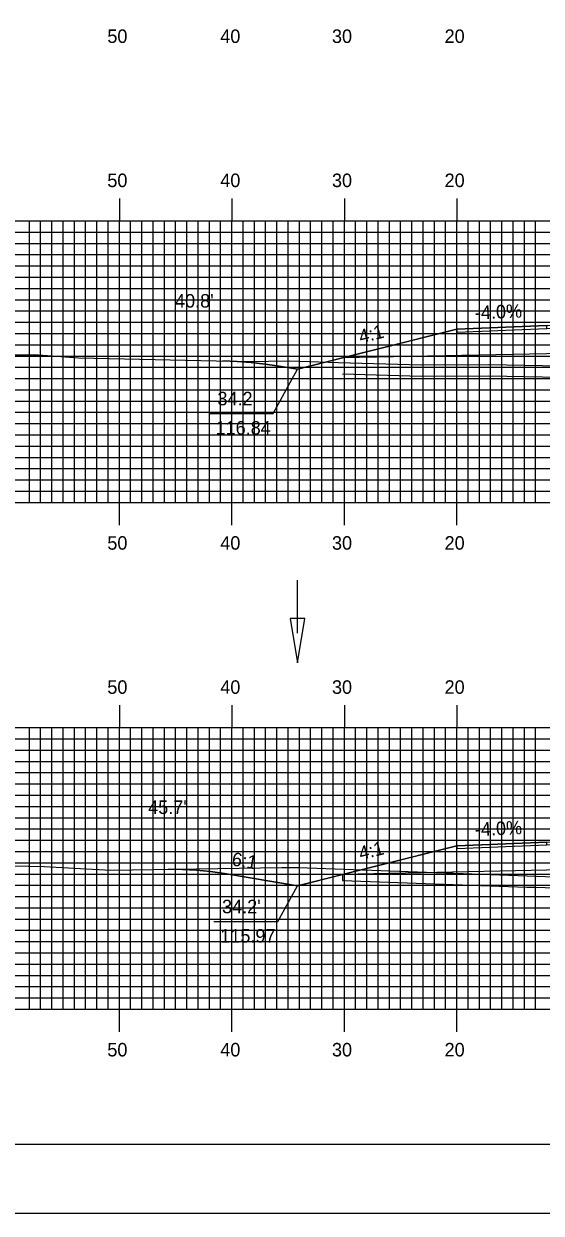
# Model space of a CAD drawing. Extents: x 1780680 to 1781023, y 442591 to 442811.
# Drawn here: x 1780786.9 to 1780832.9, y 442590.5 to 442696.2 of the extents above; entities that cross this region are included whole.
import ezdxf

# ---------------------------------------------------------------- set-up
doc = ezdxf.new("R2010")
doc.units = 0
for name, color, linetype in [('ANNOTATION', 7, 'Continuous'), ('BORDER', 7, 'Continuous'), ('D_Drainage_Ditch_Line', 7, 'Continuous'), ('D_Roadway_Centerline', 7, 'Continuous'), ('D_Roadway_Edge_Shoulder', 7, 'Continuous'), ('D_Roadway_SlopeLines', 7, 'Continuous'), ('D_Roadway_SubGrade', 7, 'Continuous'), ('D_Text_Standard', 7, 'Continuous'), ('GRUBBING IN FILL', 7, 'Continuous'), ('H_V ANNOTATION', 7, 'Continuous'), ('MAJOR', 7, 'Continuous'), ('MINOR', 7, 'Continuous'), ('PLOT BOUNDARY', 7, 'Continuous'), ('S_Roadway_Centerline', 7, 'Continuous')]:
    doc.layers.add(name, color=color, linetype=linetype)

msp = doc.modelspace()

# ---------------------------------------------------------------- linework, layer by layer
at = {"layer": 'ANNOTATION'}
for points in [[(1780803.36, 442661.56), (1780809.05, 442661.56), (1780811.21, 442665.51)], [(1780803.77, 442616.46), (1780809.46, 442616.46), (1780811.21, 442619.63)]]:
    msp.add_lwpolyline(points, dxfattribs=at)
at = {"layer": 'BORDER'}
msp.add_lwpolyline([(1780695.78, 442596.67), (1781015.78, 442596.67), (1781015.78, 442806.67), (1780695.78, 442806.67)], close=True, dxfattribs=at)
at = {"layer": 'D_Drainage_Ditch_Line'}
msp.add_line((1780811.21, 442642.05), (1780811.21, 442646.75), dxfattribs=at)
msp.add_lwpolyline([(1780811.86, 442643.36), (1780810.55, 442643.36), (1780811.21, 442639.42)], close=True, dxfattribs=at)
at = {"layer": 'D_Roadway_Centerline'}
for points in [[(1780804.59, 442666.23), (1780805.84, 442666.19), (1780807.09, 442666.1), (1780808.34, 442665.96), (1780809.59, 442665.78), (1780811.21, 442665.51), (1780815.21, 442666.51), (1780825.38, 442669.05), (1780833.38, 442669.37), (1780845.38, 442669.61), (1780857.38, 442669.37), (1780865.38, 442669.05), (1780875.56, 442666.51), (1780884.22, 442664.34)], [(1780799.73, 442621.09), (1780800.98, 442621.08), (1780802.23, 442621.02), (1780803.48, 442620.89), (1780804.73, 442620.71), (1780811.21, 442619.63), (1780815.21, 442620.63), (1780825.38, 442623.18), (1780833.38, 442623.5), (1780845.38, 442623.74), (1780857.38, 442623.5), (1780865.38, 442623.18), (1780875.56, 442620.63), (1780880.08, 442619.5)]]:
    msp.add_lwpolyline(points, dxfattribs=at)
at = {"layer": 'D_Roadway_Edge_Shoulder'}
for points in [[(1780833.38, 442669.37), (1780825.38, 442669.05), (1780825.38, 442668.8), (1780833.38, 442669.12)], [(1780833.38, 442623.5), (1780825.38, 442623.18), (1780825.38, 442622.93), (1780833.38, 442623.25)]]:
    msp.add_lwpolyline(points, close=True, dxfattribs=at)
at = {"layer": 'D_Roadway_SlopeLines'}
for points in [[(1780825.38, 442669.05), (1780811.21, 442665.51)], [(1780811.21, 442665.51), (1780809.59, 442665.78), (1780808.34, 442665.96), (1780807.09, 442666.1), (1780805.84, 442666.19), (1780804.59, 442666.23)], [(1780825.38, 442623.18), (1780811.21, 442619.63)], [(1780811.21, 442619.63), (1780804.73, 442620.71), (1780803.48, 442620.89), (1780802.23, 442621.02), (1780800.98, 442621.08), (1780799.73, 442621.09)]]:
    msp.add_lwpolyline(points, dxfattribs=at)
at = {"layer": 'D_Roadway_SubGrade'}
for points in [[(1780833.38, 442666.87), (1780815.21, 442666.51), (1780825.38, 442669.05), (1780825.38, 442668.8), (1780833.38, 442669.12), (1780845.38, 442669.36), (1780857.38, 442669.12), (1780865.38, 442668.8), (1780865.38, 442669.05), (1780875.56, 442666.51), (1780857.38, 442666.87), (1780845.38, 442667.11)], [(1780833.38, 442621), (1780815.21, 442620.63), (1780825.38, 442623.18), (1780825.38, 442622.93), (1780833.38, 442623.25), (1780845.38, 442623.49), (1780857.38, 442623.25), (1780865.38, 442622.93), (1780865.38, 442623.18), (1780875.56, 442620.63), (1780857.38, 442621), (1780845.38, 442621.24)]]:
    msp.add_lwpolyline(points, close=True, dxfattribs=at)
at = {"layer": 'GRUBBING IN FILL'}
msp.add_line((1780815.21, 442620.63), (1780815.21, 442620.09), dxfattribs=at)
msp.add_line((1780815.21, 442620.63), (1780815.21, 442620.09), dxfattribs=at)
for points in [[(1780815.21, 442665.08), (1780822.22, 442664.88), (1780828.21, 442664.92), (1780839.34, 442664.7), (1780845, 442664.49), (1780851.08, 442664.3), (1780863.46, 442663.89), (1780873.65, 442663.6), (1780875.56, 442663.55)], [(1780815.21, 442665.08), (1780822.22, 442664.88), (1780828.21, 442664.92), (1780839.34, 442664.7), (1780845, 442664.49), (1780851.08, 442664.3), (1780863.46, 442663.89), (1780873.65, 442663.6), (1780875.56, 442663.55)], [(1780815.21, 442620.09), (1780831.61, 442619.51), (1780832.44, 442619.49), (1780833.22, 442619.46), (1780853.78, 442619.04), (1780855.73, 442619.03), (1780857.73, 442618.96), (1780875.56, 442618.58)], [(1780815.21, 442620.09), (1780831.61, 442619.51), (1780832.44, 442619.49), (1780833.22, 442619.46), (1780853.78, 442619.04), (1780855.73, 442619.03), (1780857.73, 442618.96), (1780875.56, 442618.58)]]:
    msp.add_lwpolyline(points, dxfattribs=at)
at = {"layer": 'MAJOR'}
for p, q in [((1780795.38, 442680.67), (1780795.38, 442678.67)), ((1780805.38, 442680.67), (1780805.38, 442678.67)), ((1780815.38, 442680.67), (1780815.38, 442678.67)), ((1780825.38, 442680.67), (1780825.38, 442678.67)), ((1780705.38, 442678.67), (1780985.38, 442678.67)), ((1780705.38, 442678.67), (1780985.38, 442678.67)), ((1780795.38, 442653.67), (1780795.38, 442678.67)), ((1780805.38, 442653.67), (1780805.38, 442678.67)), ((1780815.38, 442653.67), (1780815.38, 442678.67)), ((1780825.38, 442653.67), (1780825.38, 442678.67)), ((1780705.38, 442673.67), (1780985.38, 442673.67)), ((1780705.38, 442668.67), (1780985.38, 442668.67)), ((1780705.38, 442663.67), (1780985.38, 442663.67)), ((1780705.38, 442658.67), (1780985.38, 442658.67)), ((1780705.38, 442653.67), (1780985.38, 442653.67)), ((1780705.38, 442653.67), (1780985.38, 442653.67)), ((1780795.38, 442651.66), (1780795.38, 442653.67)), ((1780805.38, 442651.66), (1780805.38, 442653.67)), ((1780815.38, 442651.66), (1780815.38, 442653.67)), ((1780825.38, 442651.66), (1780825.38, 442653.67)), ((1780795.38, 442635.67), (1780795.38, 442633.67)), ((1780805.38, 442635.67), (1780805.38, 442633.67)), ((1780815.38, 442635.67), (1780815.38, 442633.67)), ((1780825.38, 442635.67), (1780825.38, 442633.67)), ((1780705.38, 442633.67), (1780985.38, 442633.67)), ((1780705.38, 442633.67), (1780985.38, 442633.67)), ((1780795.38, 442608.67), (1780795.38, 442633.67)), ((1780805.38, 442608.67), (1780805.38, 442633.67)), ((1780815.38, 442608.67), (1780815.38, 442633.67)), ((1780825.38, 442608.67), (1780825.38, 442633.67)), ((1780705.38, 442628.67), (1780985.38, 442628.67)), ((1780705.38, 442623.67), (1780985.38, 442623.67)), ((1780705.38, 442618.67), (1780985.38, 442618.67)), ((1780705.38, 442613.67), (1780985.38, 442613.67)), ((1780705.38, 442608.67), (1780985.38, 442608.67)), ((1780705.38, 442608.67), (1780985.38, 442608.67)), ((1780795.38, 442606.66), (1780795.38, 442608.67)), ((1780805.38, 442606.66), (1780805.38, 442608.67)), ((1780815.38, 442606.66), (1780815.38, 442608.67)), ((1780825.38, 442606.66), (1780825.38, 442608.67))]:
    msp.add_line(p, q, dxfattribs=at)
at = {"layer": 'MINOR'}
for p, q in [((1780787.38, 442653.67), (1780787.38, 442678.67)), ((1780788.38, 442653.67), (1780788.38, 442678.67)), ((1780789.38, 442653.67), (1780789.38, 442678.67)), ((1780790.38, 442653.67), (1780790.38, 442678.67)), ((1780791.38, 442653.67), (1780791.38, 442678.67)), ((1780792.38, 442653.67), (1780792.38, 442678.67)), ((1780793.38, 442653.67), (1780793.38, 442678.67)), ((1780794.38, 442653.67), (1780794.38, 442678.67)), ((1780796.38, 442653.67), (1780796.38, 442678.67)), ((1780797.38, 442653.67), (1780797.38, 442678.67)), ((1780798.38, 442653.67), (1780798.38, 442678.67)), ((1780799.38, 442653.67), (1780799.38, 442678.67)), ((1780800.38, 442653.67), (1780800.38, 442678.67)), ((1780801.38, 442653.67), (1780801.38, 442678.67)), ((1780802.38, 442653.67), (1780802.38, 442678.67)), ((1780803.38, 442653.67), (1780803.38, 442678.67)), ((1780804.38, 442653.67), (1780804.38, 442678.67)), ((1780806.38, 442653.67), (1780806.38, 442678.67)), ((1780807.38, 442653.67), (1780807.38, 442678.67)), ((1780808.38, 442653.67), (1780808.38, 442678.67)), ((1780809.38, 442653.67), (1780809.38, 442678.67)), ((1780810.38, 442653.67), (1780810.38, 442678.67)), ((1780811.38, 442653.67), (1780811.38, 442678.67)), ((1780812.38, 442653.67), (1780812.38, 442678.67)), ((1780813.38, 442653.67), (1780813.38, 442678.67)), ((1780814.38, 442653.67), (1780814.38, 442678.67)), ((1780816.38, 442653.67), (1780816.38, 442678.67)), ((1780817.38, 442653.67), (1780817.38, 442678.67)), ((1780818.38, 442653.67), (1780818.38, 442678.67)), ((1780819.38, 442653.67), (1780819.38, 442678.67)), ((1780820.38, 442653.67), (1780820.38, 442678.67)), ((1780821.38, 442653.67), (1780821.38, 442678.67)), ((1780822.38, 442653.67), (1780822.38, 442678.67)), ((1780823.38, 442653.67), (1780823.38, 442678.67)), ((1780824.38, 442653.67), (1780824.38, 442678.67)), ((1780826.38, 442653.67), (1780826.38, 442678.67)), ((1780827.38, 442653.67), (1780827.38, 442678.67)), ((1780828.38, 442653.67), (1780828.38, 442678.67)), ((1780829.38, 442653.67), (1780829.38, 442678.67)), ((1780830.38, 442653.67), (1780830.38, 442678.67)), ((1780831.38, 442653.67), (1780831.38, 442678.67)), ((1780832.38, 442653.67), (1780832.38, 442678.67)), ((1780705.38, 442677.67), (1780985.38, 442677.67)), ((1780705.38, 442676.67), (1780985.38, 442676.67)), ((1780705.38, 442675.67), (1780985.38, 442675.67)), ((1780705.38, 442674.67), (1780985.38, 442674.67)), ((1780705.38, 442672.67), (1780985.38, 442672.67)), ((1780705.38, 442671.67), (1780985.38, 442671.67)), ((1780705.38, 442670.67), (1780985.38, 442670.67)), ((1780705.38, 442669.67), (1780985.38, 442669.67)), ((1780705.38, 442667.67), (1780985.38, 442667.67)), ((1780705.38, 442666.67), (1780985.38, 442666.67)), ((1780705.38, 442665.67), (1780985.38, 442665.67)), ((1780705.38, 442664.67), (1780985.38, 442664.67)), ((1780705.38, 442662.67), (1780985.38, 442662.67)), ((1780705.38, 442661.67), (1780985.38, 442661.67)), ((1780705.38, 442660.67), (1780985.38, 442660.67)), ((1780705.38, 442659.67), (1780985.38, 442659.67)), ((1780705.38, 442657.67), (1780985.38, 442657.67)), ((1780705.38, 442656.67), (1780985.38, 442656.67)), ((1780705.38, 442655.67), (1780985.38, 442655.67)), ((1780705.38, 442654.67), (1780985.38, 442654.67)), ((1780787.38, 442608.67), (1780787.38, 442633.67)), ((1780788.38, 442608.67), (1780788.38, 442633.67)), ((1780789.38, 442608.67), (1780789.38, 442633.67)), ((1780790.38, 442608.67), (1780790.38, 442633.67)), ((1780791.38, 442608.67), (1780791.38, 442633.67)), ((1780792.38, 442608.67), (1780792.38, 442633.67)), ((1780793.38, 442608.67), (1780793.38, 442633.67)), ((1780794.38, 442608.67), (1780794.38, 442633.67)), ((1780796.38, 442608.67), (1780796.38, 442633.67)), ((1780797.38, 442608.67), (1780797.38, 442633.67)), ((1780798.38, 442608.67), (1780798.38, 442633.67)), ((1780799.38, 442608.67), (1780799.38, 442633.67)), ((1780800.38, 442608.67), (1780800.38, 442633.67)), ((1780801.38, 442608.67), (1780801.38, 442633.67)), ((1780802.38, 442608.67), (1780802.38, 442633.67)), ((1780803.38, 442608.67), (1780803.38, 442633.67)), ((1780804.38, 442608.67), (1780804.38, 442633.67)), ((1780806.38, 442608.67), (1780806.38, 442633.67)), ((1780807.38, 442608.67), (1780807.38, 442633.67)), ((1780808.38, 442608.67), (1780808.38, 442633.67)), ((1780809.38, 442608.67), (1780809.38, 442633.67)), ((1780810.38, 442608.67), (1780810.38, 442633.67)), ((1780811.38, 442608.67), (1780811.38, 442633.67)), ((1780812.38, 442608.67), (1780812.38, 442633.67)), ((1780813.38, 442608.67), (1780813.38, 442633.67)), ((1780814.38, 442608.67), (1780814.38, 442633.67)), ((1780816.38, 442608.67), (1780816.38, 442633.67)), ((1780817.38, 442608.67), (1780817.38, 442633.67)), ((1780818.38, 442608.67), (1780818.38, 442633.67)), ((1780819.38, 442608.67), (1780819.38, 442633.67)), ((1780820.38, 442608.67), (1780820.38, 442633.67)), ((1780821.38, 442608.67), (1780821.38, 442633.67)), ((1780822.38, 442608.67), (1780822.38, 442633.67)), ((1780823.38, 442608.67), (1780823.38, 442633.67)), ((1780824.38, 442608.67), (1780824.38, 442633.67)), ((1780826.38, 442608.67), (1780826.38, 442633.67)), ((1780827.38, 442608.67), (1780827.38, 442633.67)), ((1780828.38, 442608.67), (1780828.38, 442633.67)), ((1780829.38, 442608.67), (1780829.38, 442633.67)), ((1780830.38, 442608.67), (1780830.38, 442633.67)), ((1780831.38, 442608.67), (1780831.38, 442633.67)), ((1780832.38, 442608.67), (1780832.38, 442633.67)), ((1780705.38, 442632.67), (1780985.38, 442632.67)), ((1780705.38, 442631.67), (1780985.38, 442631.67)), ((1780705.38, 442630.67), (1780985.38, 442630.67)), ((1780705.38, 442629.67), (1780985.38, 442629.67)), ((1780705.38, 442627.67), (1780985.38, 442627.67)), ((1780705.38, 442626.67), (1780985.38, 442626.67)), ((1780705.38, 442625.67), (1780985.38, 442625.67)), ((1780705.38, 442624.67), (1780985.38, 442624.67)), ((1780705.38, 442622.67), (1780985.38, 442622.67)), ((1780705.38, 442621.67), (1780985.38, 442621.67)), ((1780705.38, 442620.67), (1780985.38, 442620.67)), ((1780705.38, 442619.67), (1780985.38, 442619.67)), ((1780705.38, 442617.67), (1780985.38, 442617.67)), ((1780705.38, 442616.67), (1780985.38, 442616.67)), ((1780705.38, 442615.67), (1780985.38, 442615.67)), ((1780705.38, 442614.67), (1780985.38, 442614.67)), ((1780705.38, 442612.67), (1780985.38, 442612.67)), ((1780705.38, 442611.67), (1780985.38, 442611.67)), ((1780705.38, 442610.67), (1780985.38, 442610.67)), ((1780705.38, 442609.67), (1780985.38, 442609.67))]:
    msp.add_line(p, q, dxfattribs=at)
at = {"layer": 'PLOT BOUNDARY'}
msp.add_lwpolyline([(1780679.59, 442590.55), (1781019.59, 442590.55), (1781019.59, 442810.55), (1780679.59, 442810.55)], close=True, dxfattribs=at)
at = {"layer": 'S_Roadway_Centerline'}
for points in [[(1780784.17, 442666.78), (1780788.2, 442666.76), (1780791.74, 442666.5), (1780806.7, 442666.19), (1780810.54, 442666.23), (1780814.82, 442666.09), (1780822.24, 442665.88), (1780828.21, 442665.92), (1780839.37, 442665.7), (1780845.04, 442665.49), (1780851.11, 442665.3), (1780863.49, 442664.89), (1780873.68, 442664.6), (1780886.04, 442664.3), (1780891.46, 442664.18), (1780897.29, 442663.85)], [(1780776.03, 442621.59), (1780788.7, 442621.33), (1780794.62, 442621.01), (1780809.82, 442621.25), (1780810.61, 442621.26), (1780811.31, 442621.24), (1780831.63, 442620.51), (1780832.47, 442620.49), (1780833.25, 442620.46), (1780853.79, 442620.04), (1780855.75, 442620.03), (1780857.76, 442619.96), (1780876.41, 442619.56), (1780879.04, 442619.51), (1780881.97, 442619.49), (1780891.24, 442619.25), (1780899.31, 442619.06)]]:
    msp.add_lwpolyline(points, dxfattribs=at)

# ---------------------------------------------------------------- texts
at = {"layer": 'ANNOTATION'}
for s, rotation, p in [('-4.0%', 2.2906, (1780827.01, 442669.92)), ('4:1', 14.0362, (1780816.83, 442667.78)), ('-4.0%', 2.2906, (1780827.01, 442624.04)), ('6:1', 350.5377, (1780805.31, 442621.44)), ('4:1', 14.0362, (1780816.83, 442621.9))]:
    msp.add_text(s, height=1.2, rotation=rotation, dxfattribs=at).set_placement(p)
for s, p in [("34.2'", (1780804.1, 442662.29)), ('116.84', (1780803.93, 442659.69)), ("34.2'", (1780804.51, 442617.18)), ('115.97', (1780804.35, 442614.58))]:
    msp.add_text(s, height=1.2, dxfattribs=at).set_placement(p)
at = {"layer": 'D_Text_Standard'}
for s, p in [("40.8'", (1780800.33, 442670.97)), ("45.7'", (1780797.94, 442626))]:
    msp.add_text(s, height=1.2, dxfattribs=at).set_placement(p)
at = {"layer": 'H_V ANNOTATION'}
for s, p in [('50', (1780794.31, 442694.47)), ('40', (1780804.35, 442694.47)), ('30', (1780814.28, 442694.47)), ('20', (1780824.29, 442694.47)), ('50', (1780794.31, 442681.67)), ('40', (1780804.35, 442681.67)), ('30', (1780814.28, 442681.67)), ('20', (1780824.29, 442681.67)), ('50', (1780794.31, 442649.47)), ('40', (1780804.35, 442649.47)), ('30', (1780814.28, 442649.47)), ('20', (1780824.29, 442649.47)), ('50', (1780794.31, 442636.67)), ('40', (1780804.35, 442636.67)), ('30', (1780814.28, 442636.67)), ('20', (1780824.29, 442636.67)), ('50', (1780794.31, 442604.47)), ('40', (1780804.35, 442604.47)), ('30', (1780814.28, 442604.47)), ('20', (1780824.29, 442604.47))]:
    msp.add_text(s, height=1.2, dxfattribs=at).set_placement(p)

doc.saveas('drawing.dxf')
